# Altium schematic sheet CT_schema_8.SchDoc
size 401 x 301 mm
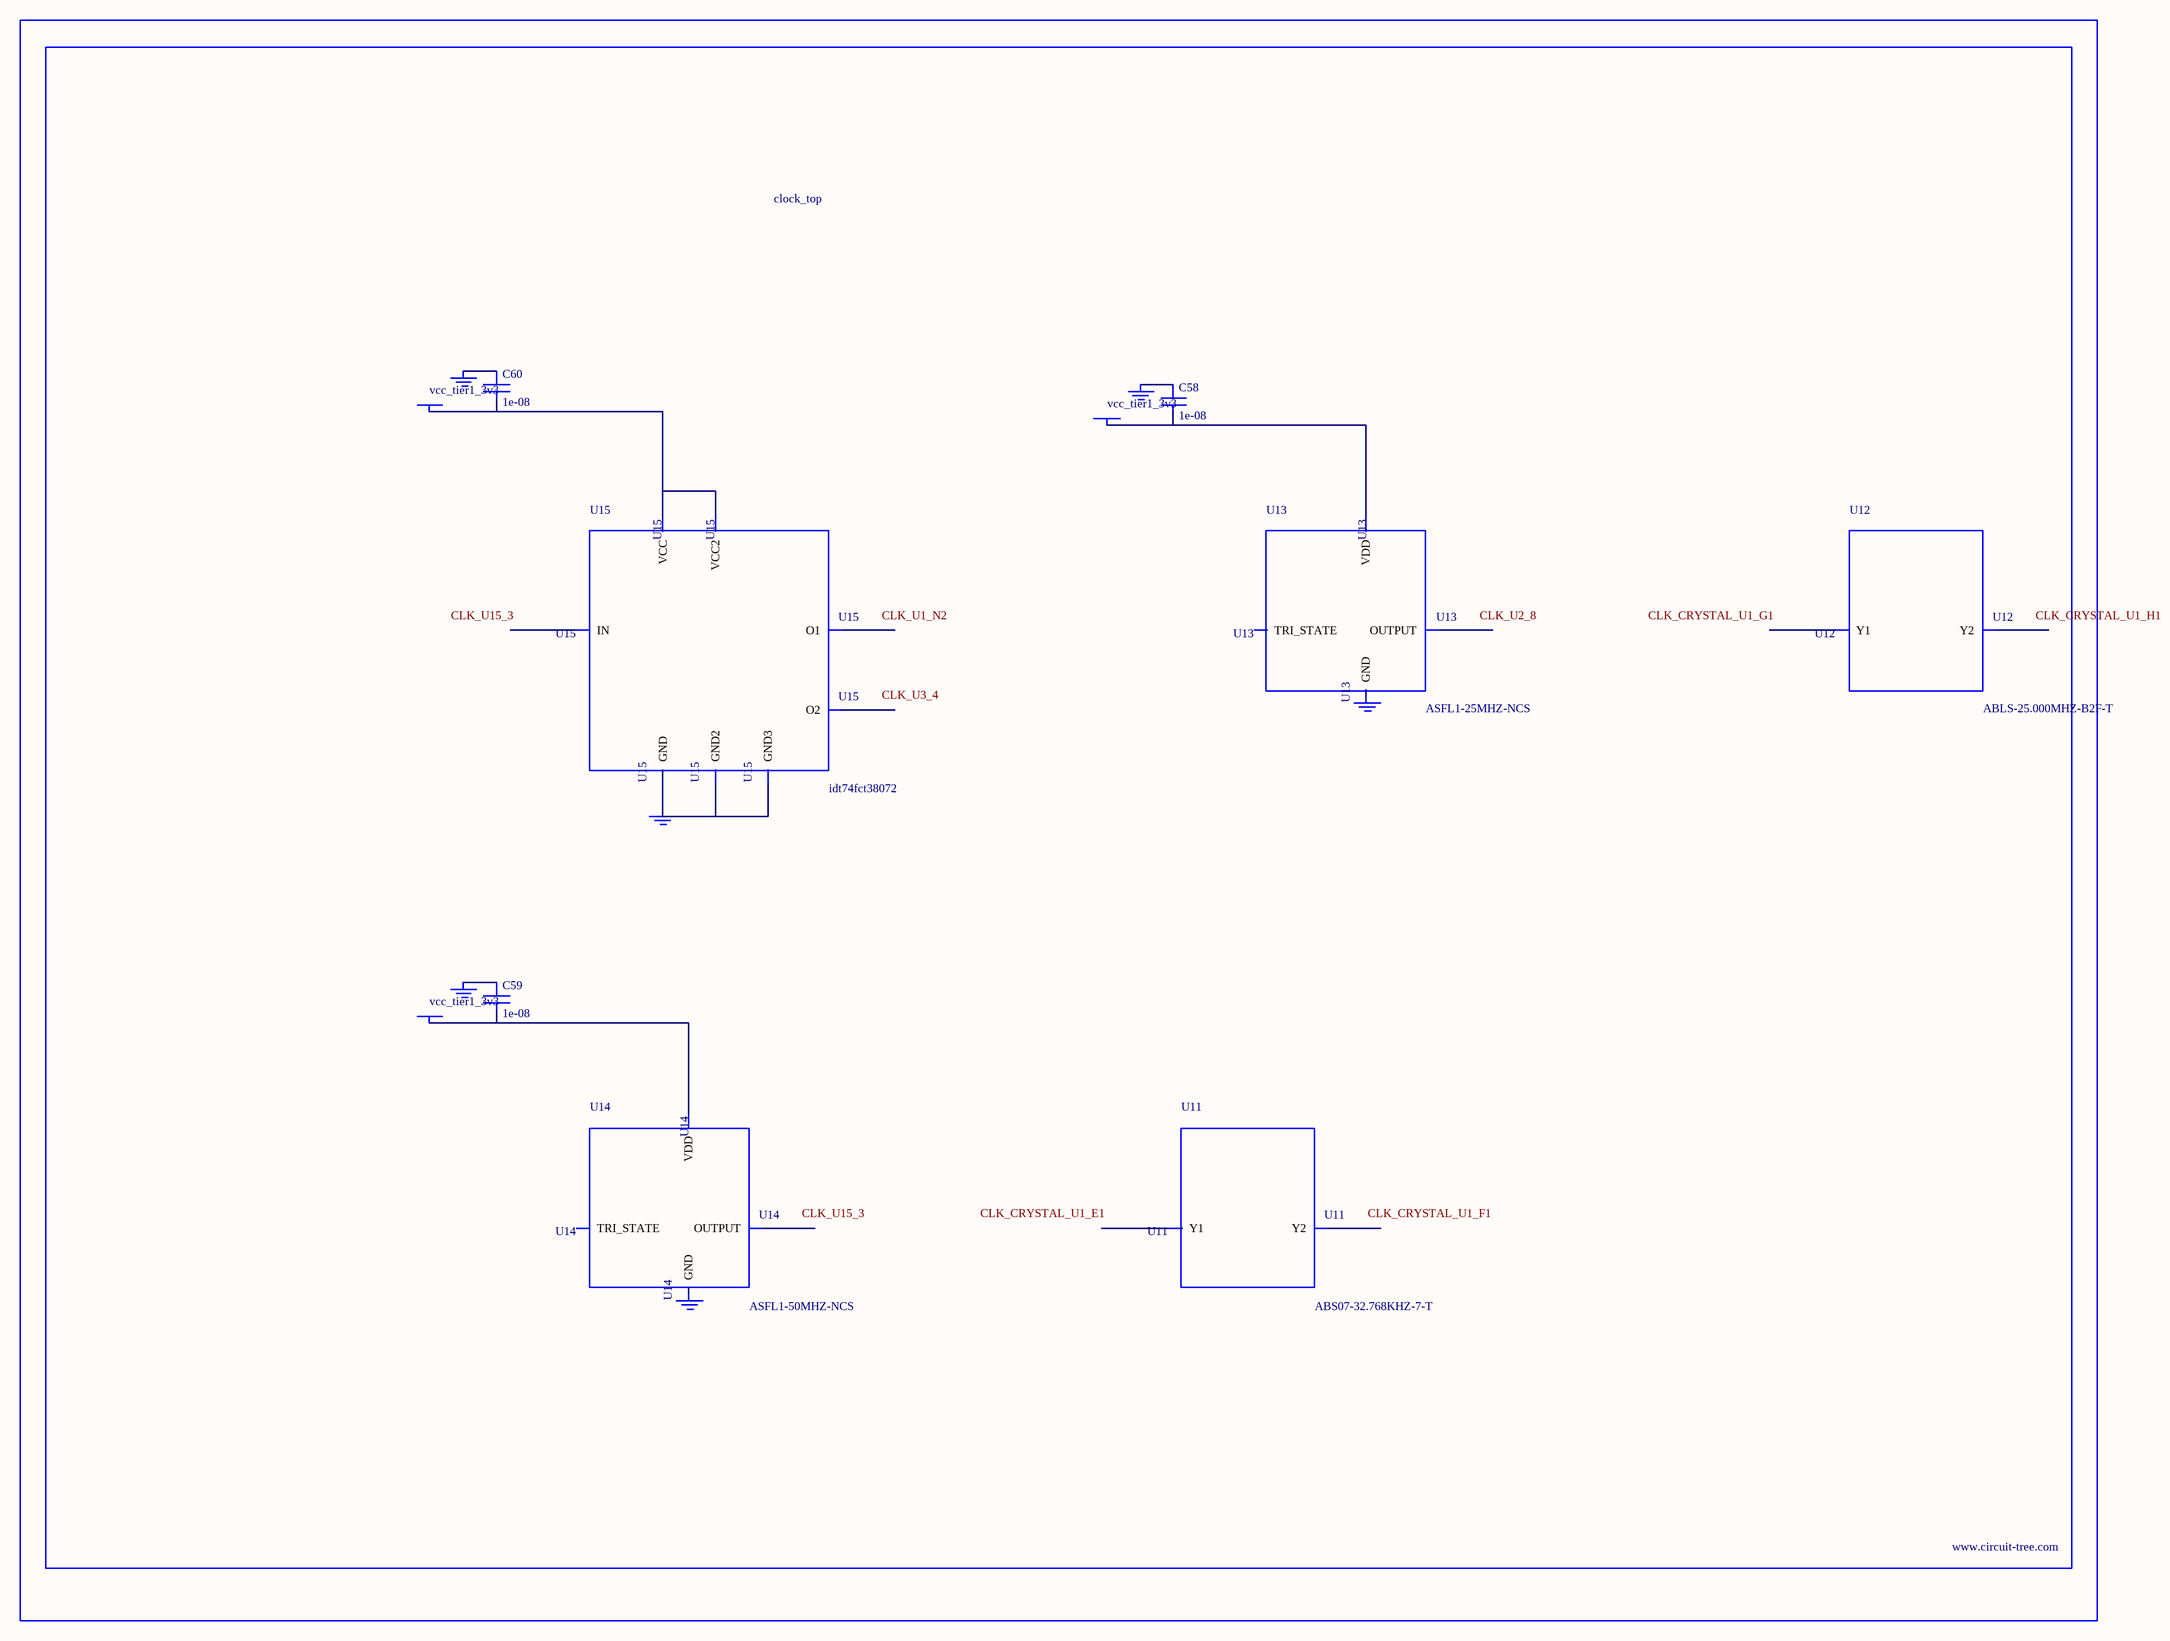
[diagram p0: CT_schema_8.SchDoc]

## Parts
BORDER7  (no value)
C58  1e-08  [C0402]
C59  1e-08  [C0402]
C60  1e-08  [C0402]
GND_INSTANCE_7_0  (no value)
GND_INSTANCE_7_1  (no value)
GND_INSTANCE_7_2  (no value)
GND_INSTANCE_7_3  (no value)
GND_INSTANCE_7_4  (no value)
GND_INSTANCE_7_5  (no value)
POWER_INSTANCE_7_0  vcc_tier1_3v3
POWER_INSTANCE_7_1  vcc_tier1_3v3
POWER_INSTANCE_7_2  vcc_tier1_3v3
U11  ABS07-32.768KHZ-7-T  [ABS07-32.768KHZ-7-T]
U12  ABLS-25.000MHZ-B2F-T  [ABLS-25.000MHZ-B2F-T]
U13  ASFL1-25MHZ-NCS  [ASFL1]
U14  ASFL1-50MHZ-NCS  [ASFL1]
U15  idt74fct38072  [IDT74FCT38072]

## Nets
NetC58_1: C58.1 GND_INSTANCE_7_0.0(GND)
NetC58_2: C58.2 POWER_INSTANCE_7_0.0(PWR) U13.4(VDD)
NetC59_1: C59.1 GND_INSTANCE_7_2.0(GND)
NetC59_2: C59.2 POWER_INSTANCE_7_1.0(PWR) U14.4(VDD)
NetC60_1: C60.1 GND_INSTANCE_7_4.0(GND)
NetC60_2: C60.2 POWER_INSTANCE_7_2.0(PWR) U15.1(VCC) U15.2(VCC2)
NetGND_INSTANCE_7_5_0: GND_INSTANCE_7_5.0(GND) U15.4(GND) U15.5(GND2) U15.8(GND3)

Not connected (* = marked no-connect by the designer): GND_INSTANCE_7_1 0(GND); GND_INSTANCE_7_3 0(GND); U11 1(Y1) 2(Y2); U12 1(Y1) 2(Y2); U13 1(TRI_STATE) 2(GND) 3(OUTPUT); U14 1(TRI_STATE) 2(GND) 3(OUTPUT); U15 3(IN) 6(O2) 7(O1)

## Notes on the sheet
- Labels drawn without touching a wire or pin: CLK_CRYSTAL_U1_E1, CLK_CRYSTAL_U1_F1, CLK_CRYSTAL_U1_G1, CLK_CRYSTAL_U1_H1, CLK_U1_N2, CLK_U2_8, CLK_U3_4, CLK_U15_3

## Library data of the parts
BORDER7 = BORDER_PAGE7
C58-C60 = C0402C103K3RAC
GND_INSTANCE_7_0-GND_INSTANCE_7_5 = GND
POWER_INSTANCE_7_0-POWER_INSTANCE_7_2 = PWR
